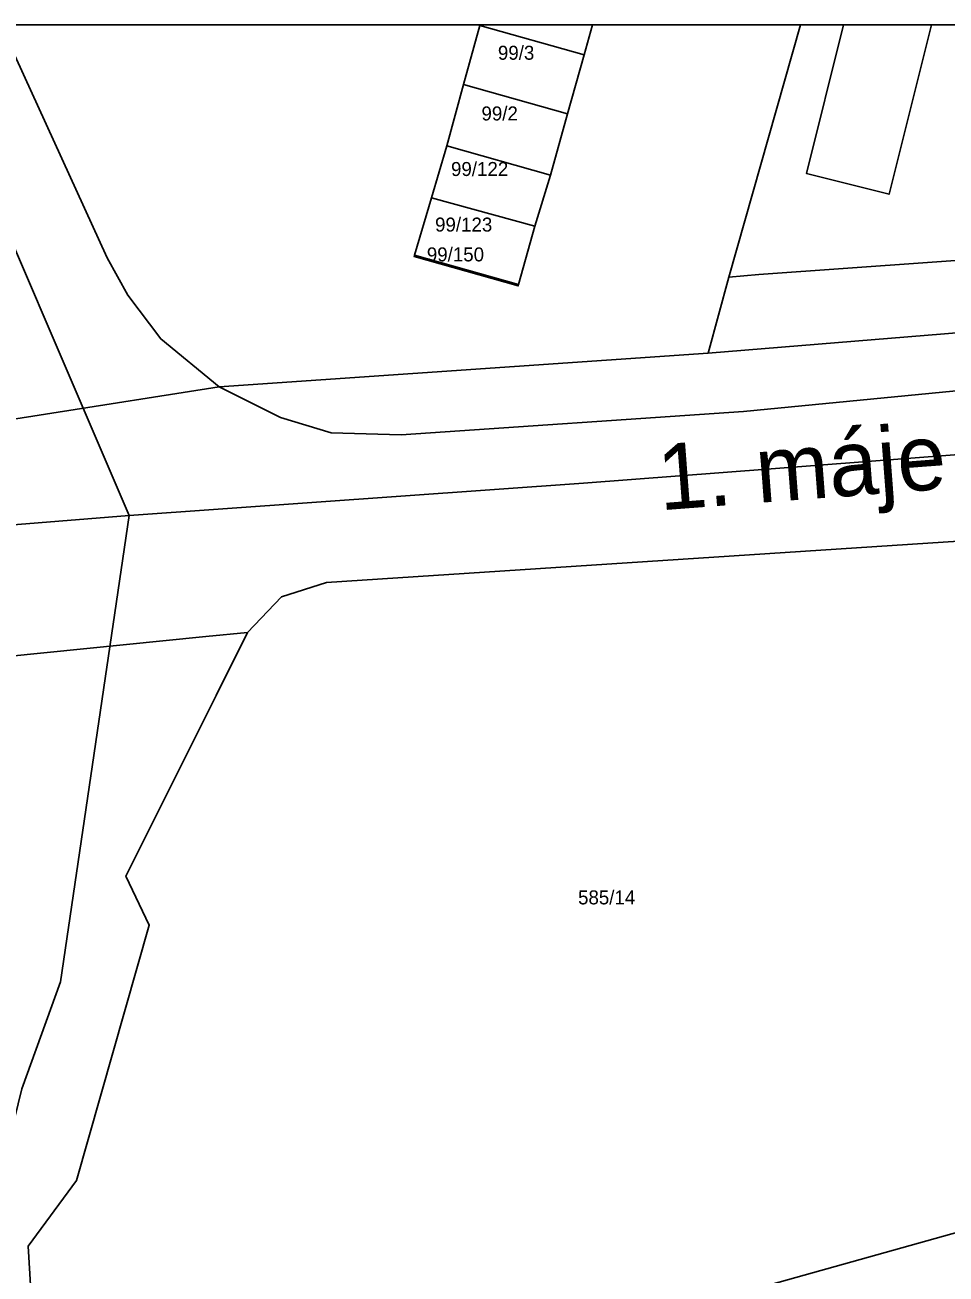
# Model space of a CAD drawing. Extents: x -873642 to -872917, y -1012962 to -1012567.
# Drawn here: x -873065.9 to -873009.9, y -1012643.4 to -1012567.5 of the extents above; entities that cross this region are included whole.
import ezdxf

# ---------------------------------------------------------------- set-up
doc = ezdxf.new("R2010")
doc.units = 0
for name, color, linetype in [('cisla_parcelni_kn', 7, 'Continuous'), ('osy_ulic', 7, 'Continuous'), ('parcely_kn', 7, 'Continuous'), ('stavebni_objekty_ostatni', 7, 'Continuous'), ('stavebni_objekty_vyroba', 7, 'Continuous'), ('ulice', 7, 'Continuous')]:
    doc.layers.add(name, color=color, linetype=linetype)

msp = doc.modelspace()

# ---------------------------------------------------------------- linework, layer by layer
at = {"layer": 'osy_ulic'}
for points in [[(-873059.56, -1012597.3), (-873070.62, -1012571.55), (-873072.355, -1012567.5)], [(-872916.927, -1012586.659), (-872957.62, -1012590.24), (-872977.73, -1012591.46), (-872994.83, -1012592.51), (-873031.96, -1012595.34), (-873059.56, -1012597.3), (-873096.52, -1012600.28), (-873281.07, -1012614.36), (-873481.95, -1012629.68)], [(-873411.85, -1012822.53), (-873317.85, -1012788.44), (-873277.23, -1012773.91), (-873252.76, -1012767.01), (-873201.18, -1012755.57), (-873115.6, -1012739.3), (-873104.65, -1012731.3), (-873088.93, -1012706.26), (-873080.41, -1012681.66), (-873071.61, -1012653.78), (-873070.57, -1012650.45), (-873066.08, -1012632.13), (-873063.74, -1012625.63), (-873059.56, -1012597.3)]]:
    msp.add_lwpolyline(points, dxfattribs=at)
at = {"layer": 'parcely_kn'}
for p, q in [((-873038.242, -1012567.5), (-873067.358, -1012567.5)), ((-873038.242, -1012567.5), (-873067.358, -1012567.5)), ((-873031.41, -1012567.5), (-873038.242, -1012567.5)), ((-873031.41, -1012567.5), (-873038.242, -1012567.5)), ((-873018.763, -1012567.5), (-873031.41, -1012567.5)), ((-873018.763, -1012567.5), (-873031.41, -1012567.5)), ((-873016.145, -1012567.5), (-873018.763, -1012567.5)), ((-873016.145, -1012567.5), (-873018.763, -1012567.5)), ((-873010.799, -1012567.5), (-873016.145, -1012567.5)), ((-873010.799, -1012567.5), (-873016.145, -1012567.5)), ((-873004.031, -1012567.5), (-873010.799, -1012567.5)), ((-873004.031, -1012567.5), (-873010.799, -1012567.5))]:
    msp.add_line(p, q, dxfattribs=at)
for points in [[(-873075.21, -1012592.8), (-873054.1, -1012589.49), (-873057.64, -1012586.57), (-873059.64, -1012583.92), (-873060.9, -1012581.64), (-873067.358, -1012567.5)], [(-873075.21, -1012592.8), (-873054.1, -1012589.49), (-873057.64, -1012586.57), (-873059.64, -1012583.92), (-873060.9, -1012581.64), (-873067.358, -1012567.5)], [(-873067.358, -1012567.5), (-873060.9, -1012581.64), (-873059.64, -1012583.92), (-873057.64, -1012586.57), (-873054.1, -1012589.49), (-873024.38, -1012587.43), (-873023.12, -1012582.82), (-873018.763, -1012567.5)], [(-873067.358, -1012567.5), (-873060.9, -1012581.64), (-873059.64, -1012583.92), (-873057.64, -1012586.57), (-873054.1, -1012589.49), (-873024.38, -1012587.43), (-873023.12, -1012582.82), (-873018.763, -1012567.5)], [(-873031.41, -1012567.5), (-873031.92, -1012569.32), (-873032.92, -1012572.9), (-873033.96, -1012576.62), (-873034.9, -1012579.72), (-873035.9, -1012583.26), (-873035.92, -1012583.35), (-873042.24, -1012581.57), (-873042.22, -1012581.49), (-873041.19, -1012578), (-873040.26, -1012574.84), (-873039.24, -1012571.12), (-873038.25, -1012567.53), (-873038.242, -1012567.5)], [(-873031.41, -1012567.5), (-873031.92, -1012569.32), (-873032.92, -1012572.9), (-873033.96, -1012576.62), (-873034.9, -1012579.72), (-873035.9, -1012583.26), (-873035.92, -1012583.35), (-873042.24, -1012581.57), (-873042.22, -1012581.49), (-873041.19, -1012578), (-873040.26, -1012574.84), (-873039.24, -1012571.12), (-873038.25, -1012567.53), (-873038.242, -1012567.5)], [(-873038.242, -1012567.5), (-873038.25, -1012567.53), (-873031.92, -1012569.32), (-873031.41, -1012567.5)], [(-873038.242, -1012567.5), (-873038.25, -1012567.53), (-873031.92, -1012569.32), (-873031.41, -1012567.5)], [(-873018.763, -1012567.5), (-873023.12, -1012582.82), (-873021.3, -1012582.65), (-873005.64, -1012581.55), (-873005.55, -1012580.78), (-873004.031, -1012567.5)], [(-873018.763, -1012567.5), (-873023.12, -1012582.82), (-873021.3, -1012582.65), (-873005.64, -1012581.55), (-873005.55, -1012580.78), (-873004.031, -1012567.5)], [(-873016.145, -1012567.5), (-873018.41, -1012576.52), (-873013.38, -1012577.78), (-873010.799, -1012567.5)], [(-873010.799, -1012567.5), (-873013.38, -1012577.78), (-873018.41, -1012576.52), (-873016.145, -1012567.5)], [(-873016.145, -1012567.5), (-873018.41, -1012576.52), (-873013.38, -1012577.78), (-873010.799, -1012567.5)], [(-873010.799, -1012567.5), (-873013.38, -1012577.78), (-873018.41, -1012576.52), (-873016.145, -1012567.5)], [(-872916.927, -1012575.02), (-872927.42, -1012575.9), (-872948.82, -1012577.56), (-872966.78, -1012578.95), (-872967.8, -1012579), (-872979.96, -1012579.73), (-872989.6, -1012580.34), (-873005.64, -1012581.55), (-873021.3, -1012582.65), (-873023.12, -1012582.82), (-873024.38, -1012587.43), (-872916.927, -1012578.644)], [(-872916.927, -1012575.02), (-872927.42, -1012575.9), (-872948.82, -1012577.56), (-872966.78, -1012578.95), (-872967.8, -1012579), (-872979.96, -1012579.73), (-872989.6, -1012580.34), (-873005.64, -1012581.55), (-873021.3, -1012582.65), (-873023.12, -1012582.82), (-873024.38, -1012587.43), (-872916.927, -1012578.644)], [(-872916.927, -1012578.644), (-873024.38, -1012587.43), (-873054.1, -1012589.49), (-873050.36, -1012591.35), (-873047.29, -1012592.28), (-873043.04, -1012592.4), (-873022.23, -1012590.98), (-872995.95, -1012588.42), (-872974.01, -1012587.35), (-872955.82, -1012586.14), (-872931.53, -1012584.18), (-872916.927, -1012583.057)], [(-872916.927, -1012578.644), (-873024.38, -1012587.43), (-873054.1, -1012589.49), (-873050.36, -1012591.35), (-873047.29, -1012592.28), (-873043.04, -1012592.4), (-873022.23, -1012590.98), (-872995.95, -1012588.42), (-872974.01, -1012587.35), (-872955.82, -1012586.14), (-872931.53, -1012584.18), (-872916.927, -1012583.057)], [(-872916.927, -1012583.057), (-872931.53, -1012584.18), (-872955.82, -1012586.14), (-872974.01, -1012587.35), (-872995.95, -1012588.42), (-873022.23, -1012590.98), (-873043.04, -1012592.4), (-873047.29, -1012592.28), (-873050.36, -1012591.35), (-873054.1, -1012589.49), (-873075.21, -1012592.8), (-873143.44, -1012597.91), (-873216.55, -1012603.73)], [(-873273.72, -1012619.94), (-873079.43, -1012607.12), (-873054.9, -1012604.66), (-873052.37, -1012604.41), (-873050.31, -1012602.24), (-873047.57, -1012601.38), (-872987.5, -1012597.44), (-872986.52, -1012596.03), (-872985.48, -1012595.15), (-872984.31, -1012594.39), (-872970.43, -1012593.36), (-872967.88, -1012593.04), (-872950.87, -1012593.5), (-872930.93, -1012593.98), (-872925.9, -1012594.03), (-872921.95, -1012593.97), (-872917.07, -1012593.66), (-872916.927, -1012593.651)], [(-873079.43, -1012607.12), (-873054.9, -1012604.66), (-873052.37, -1012604.41), (-873054.28, -1012608.24), (-873059.76, -1012619.22), (-873058.34, -1012622.19), (-873062.75, -1012637.7), (-873065.7, -1012641.7), (-873065.38, -1012647.07), (-873066.31, -1012649.31), (-873079.09, -1012694.9), (-873083.74, -1012706.73), (-873087.64, -1012713.81), (-873091.65, -1012719.56), (-873097.47, -1012726.79), (-873099.7, -1012729.49), (-873101.03, -1012731.11), (-873105.65, -1012736.17), (-873110.07, -1012739.5), (-873114.5, -1012741.96), (-873122.26, -1012744.11), (-873135.01, -1012746.72), (-873148.18, -1012749.22), (-873185.58, -1012756.25)], [(-873079.43, -1012607.12), (-873054.9, -1012604.66), (-873052.37, -1012604.41), (-873054.28, -1012608.24), (-873059.76, -1012619.22), (-873058.34, -1012622.19), (-873062.75, -1012637.7), (-873065.7, -1012641.7), (-873065.38, -1012647.07), (-873066.31, -1012649.31), (-873079.09, -1012694.9), (-873083.74, -1012706.73), (-873087.64, -1012713.81), (-873091.65, -1012719.56), (-873097.47, -1012726.79), (-873099.7, -1012729.49), (-873101.03, -1012731.11), (-873105.65, -1012736.17), (-873110.07, -1012739.5), (-873114.5, -1012741.96), (-873122.26, -1012744.11), (-873135.01, -1012746.72), (-873148.18, -1012749.22), (-873185.58, -1012756.25)], [(-873026.14, -1012645.58), (-872990.98, -1012635.74)], [(-873026.14, -1012645.58), (-872990.98, -1012635.74)]]:
    msp.add_lwpolyline(points, dxfattribs=at)
for points in [[(-873031.92, -1012569.32), (-873032.92, -1012572.9), (-873039.24, -1012571.12), (-873038.25, -1012567.53)], [(-873031.92, -1012569.32), (-873032.92, -1012572.9), (-873039.24, -1012571.12), (-873038.25, -1012567.53)], [(-873039.24, -1012571.12), (-873032.92, -1012572.9), (-873033.96, -1012576.62), (-873040.26, -1012574.84)], [(-873039.24, -1012571.12), (-873032.92, -1012572.9), (-873033.96, -1012576.62), (-873040.26, -1012574.84)], [(-873040.26, -1012574.84), (-873033.96, -1012576.62), (-873034.9, -1012579.72), (-873041.19, -1012578)], [(-873040.26, -1012574.84), (-873033.96, -1012576.62), (-873034.9, -1012579.72), (-873041.19, -1012578)], [(-873041.19, -1012578), (-873034.9, -1012579.72), (-873035.9, -1012583.26), (-873042.22, -1012581.49)], [(-873041.19, -1012578), (-873034.9, -1012579.72), (-873035.9, -1012583.26), (-873042.22, -1012581.49)], [(-873035.9, -1012583.26), (-873035.92, -1012583.35), (-873042.24, -1012581.57), (-873042.22, -1012581.49)], [(-873035.9, -1012583.26), (-873035.92, -1012583.35), (-873042.24, -1012581.57), (-873042.22, -1012581.49)], [(-873047.57, -1012601.38), (-872987.5, -1012597.44), (-872963.92, -1012595.9), (-872964.43, -1012596.64), (-872989.57, -1012634.71), (-872990.98, -1012635.74), (-873026.14, -1012645.58), (-873065.38, -1012647.07), (-873065.7, -1012641.7), (-873062.75, -1012637.7), (-873058.34, -1012622.19), (-873059.76, -1012619.22), (-873054.28, -1012608.24), (-873052.37, -1012604.41), (-873050.31, -1012602.24)], [(-873047.57, -1012601.38), (-872987.5, -1012597.44), (-872963.92, -1012595.9), (-872964.43, -1012596.64), (-872989.57, -1012634.71), (-872990.98, -1012635.74), (-873026.14, -1012645.58), (-873065.38, -1012647.07), (-873065.7, -1012641.7), (-873062.75, -1012637.7), (-873058.34, -1012622.19), (-873059.76, -1012619.22), (-873054.28, -1012608.24), (-873052.37, -1012604.41), (-873050.31, -1012602.24)]]:
    msp.add_lwpolyline(points, close=True, dxfattribs=at)
at = {"layer": 'stavebni_objekty_ostatni'}
msp.add_line((-873031.41, -1012567.5), (-873038.242, -1012567.5), dxfattribs=at)
for points in [[(-873031.92, -1012569.32), (-873032.92, -1012572.9), (-873039.24, -1012571.12), (-873038.25, -1012567.53)], [(-873039.24, -1012571.12), (-873032.92, -1012572.9), (-873033.96, -1012576.62), (-873040.26, -1012574.84)], [(-873040.26, -1012574.84), (-873033.96, -1012576.62), (-873034.9, -1012579.72), (-873041.19, -1012578)], [(-873041.19, -1012578), (-873034.9, -1012579.72), (-873035.9, -1012583.26), (-873042.22, -1012581.49)]]:
    msp.add_lwpolyline(points, close=True, dxfattribs=at)
msp.add_lwpolyline([(-873038.242, -1012567.5), (-873038.25, -1012567.53), (-873031.92, -1012569.32), (-873031.41, -1012567.5)], dxfattribs=at)
at = {"layer": 'stavebni_objekty_vyroba'}
msp.add_line((-873010.799, -1012567.5), (-873016.145, -1012567.5), dxfattribs=at)
msp.add_lwpolyline([(-873016.145, -1012567.5), (-873018.41, -1012576.52), (-873013.38, -1012577.78), (-873010.799, -1012567.5)], dxfattribs=at)

# ---------------------------------------------------------------- texts
at = {"layer": 'cisla_parcelni_kn'}
for s, p in [('99/3', (-873037.152, -1012569.613)), ('99/3', (-873037.152, -1012569.613)), ('99/2', (-873038.152, -1012573.3)), ('99/2', (-873038.152, -1012573.3)), ('99/122', (-873040.002, -1012576.675)), ('99/122', (-873040.002, -1012576.675)), ('99/123', (-873040.971, -1012580.05)), ('99/123', (-873040.971, -1012580.05)), ('99/150', (-873041.471, -1012581.863)), ('99/150', (-873041.471, -1012581.863)), ('585/14', (-873032.283, -1012620.925)), ('585/14', (-873032.283, -1012620.925))]:
    msp.add_text(s, height=0.85, dxfattribs=at).set_placement(p)
at = {"layer": 'ulice'}
msp.add_text('1. máje', height=4, rotation=4.35858, dxfattribs=at).set_placement((-873027.291, -1012596.99))

doc.saveas('drawing.dxf')
